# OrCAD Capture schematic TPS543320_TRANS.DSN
size D; title: TPS543320: 4-V to 18-V Input, 3-A Synchronous Step-Down Converter; rev: 1.0; note: Datasheet: SLUSEE1A     EVM: SLVUC07A; note: Internally Compensated Advanced Current Mode Control
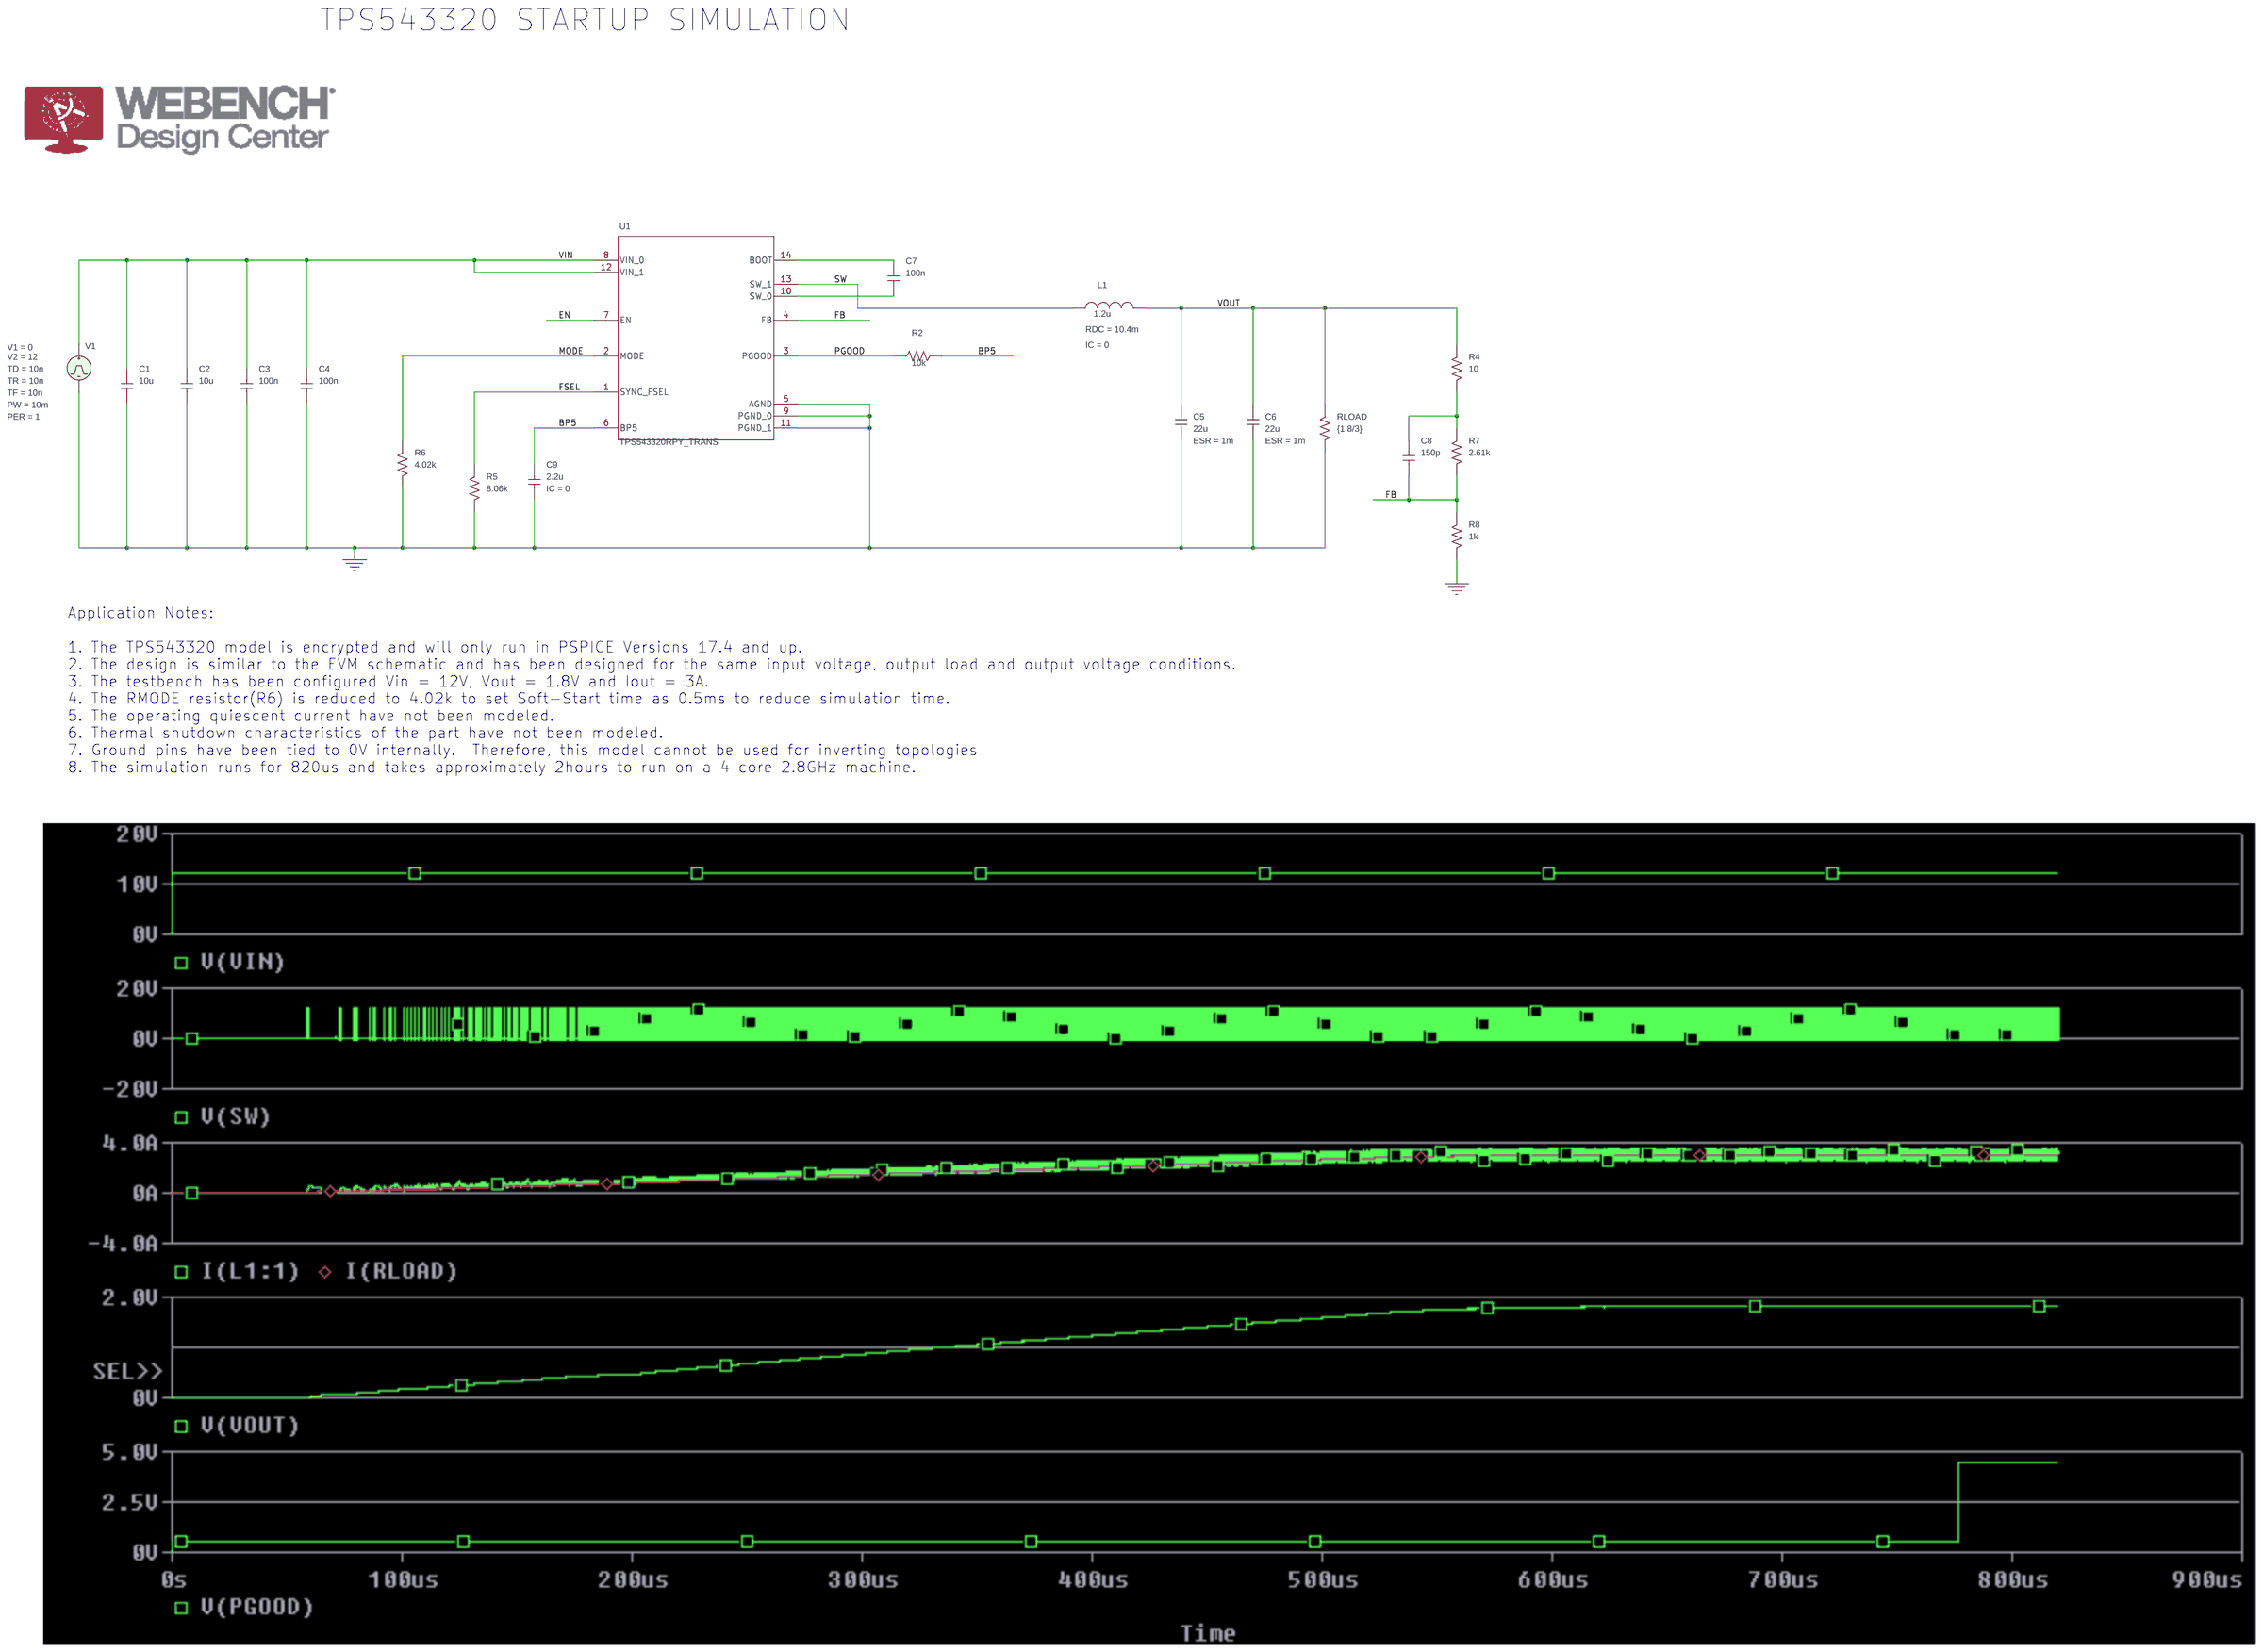
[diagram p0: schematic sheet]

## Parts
C1  10u  [cap196]
C2  10u  [cap196]
C3  100n  [cap196]
C4  100n  [cap196]
C5  22u  [RAD/CK05]
C6  22u  [RAD/CK05]
C7  100n  [cap196]
C8  150p  [cap196]
C9  2.2u  [cap196]
L1  1.2u  [DISC/.350x.175/LS.200x.100/.034]
R2  10k  [AXRC05]
R4  10  [AXRC05]
R5  8.06k  [AXRC05]
R6  4.02k  [AXRC05]
R7  2.61k  [AXRC05]
R8  1k  [AXRC05]
RLOAD  {1.8/3}  [AXRC05]
U1  TPS543320RPY_TRANS  [RPY0014A-MFG]
V1  VPULSE

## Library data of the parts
C1-C4 C7 C8 = C
C5 C6 = C: AppProp: InductiveSlave:;SRF:;PrevCap:22u;PrevESL:; ESR: 1m; IC: 0
C9 = C: IC: 0
L1 = L: AppProp: SRF:; IC: 0; RDC: 10.4m
R2 R4-R8 RLOAD = R
U1 = TPS543320RPY_TRANS
V1 = VPULSE: PER: 1; PW: 10m; TD: 10n; TF: 10n; TR: 10n; V1: 0; V2: 12

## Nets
VIN: C1.1 C2.1 C3.1 C4.1 U1.8(VIN_0) U1.12(VIN_1) V1.1(+)
0: C1.2 C2.2 C3.2 C4.2 C5.2 C6.2 C9.2 R5.2 R6.2 R8.2 RLOAD.2 U1.5(AGND) U1.9(PGND_0) U1.11(PGND_1) V1.2(-)
BP5: C9.1 R2.2 U1.6(BP5)
EN: U1.7(EN)
FB: C8.2 R7.2 R8.1 U1.4(FB)
FSEL: R5.1 U1.1(SYNC_FSEL)
MODE: R6.1 U1.2(MODE)
PGOOD: R2.1 U1.3(PGOOD)
SW: L1.1 U1.13(SW_1)
VOUT: C5.1 C6.1 L1.2 R4.1 RLOAD.1
N16771999: C7.1 U1.14(BOOT)
N16772003: C7.2 U1.10(SW_0)
N16772420: C8.1 R4.2 R7.1

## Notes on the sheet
- TPS543320 STARTUP SIMULATION
- Application Notes:
  1. The TPS543320 model is encrypted and will only run in PSPICE Versions 17.4 and up.
  2. The design is similar to the EVM schematic and has been designed for the same input voltage, output load and output voltage conditions.
  3. The testbench has been configured Vin = 12V, Vout = 1.8V and Iout = 3A.
  4. The RMODE resistor(R6) is reduced to 4.02k to set Soft-Start time as 0.5ms to reduce simulation time.
  5. The operating quiescent current have not been modeled.
  6. Thermal shutdown characteristics of the part have not been modeled.
  7. Ground pins have been tied to 0V internally.  Therefore, this model cannot be used for inverting topologies
  8. The simulation runs for 820us and takes approximately 2hours to run on a 4 core 2.8GHz machine.
